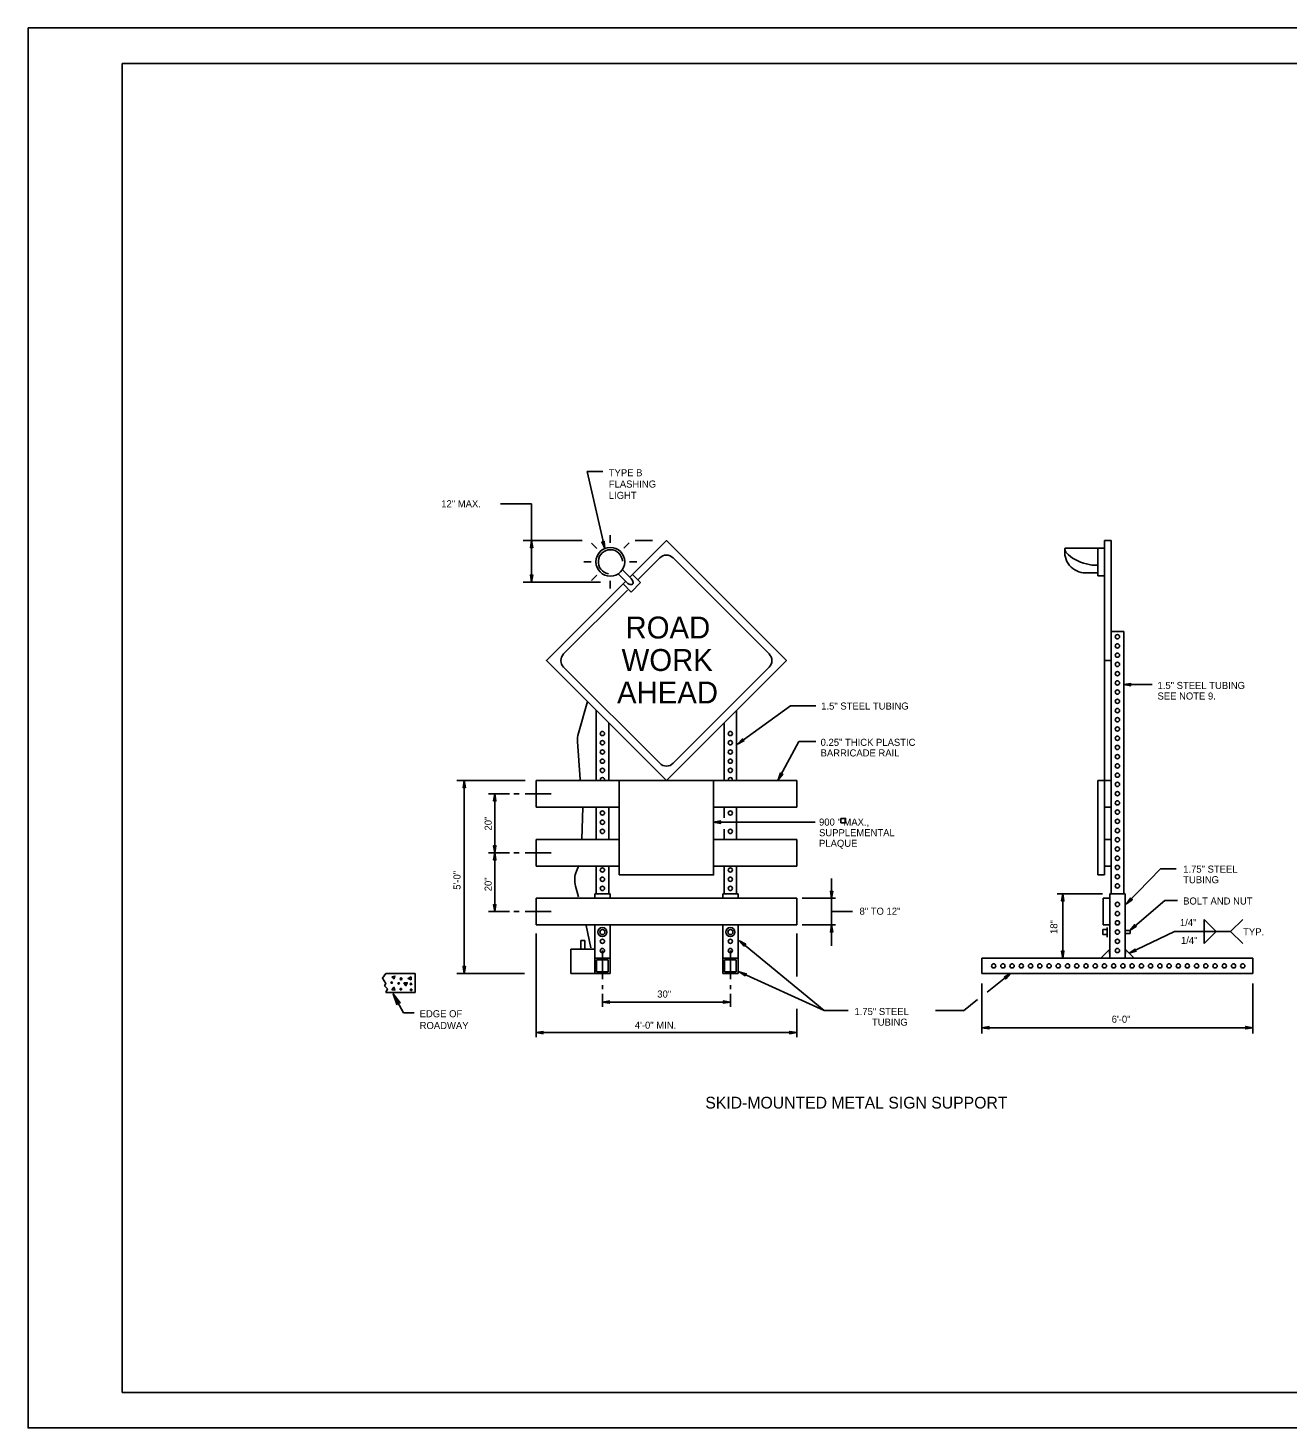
# Model space of a CAD drawing. Extents: x 641885 to 642934, y 293121 to 294294.
# Drawn here: x 641885 to 642420, y 293700 to 294294 of the extents above; entities that cross this region are included whole.
import ezdxf

# ---------------------------------------------------------------- set-up
doc = ezdxf.new("R2010")
doc.units = 0
for name, color, linetype in [('1', 7, 'Continuous'), ('Default', 7, 'Continuous'), ('Level 1', 7, 'Continuous'), ('Level 2', 7, 'Continuous'), ('Level 3', 7, 'Continuous'), ('PLT-BNDY', 7, 'Continuous')]:
    doc.layers.add(name, color=color, linetype=linetype)

# ---------------------------------------------------------------- blocks, each defined once
blk = doc.blocks.new('RARROW')
at = {"layer": 'Level 3'}
blk.add_lwpolyline([(-2.2695, 0.285), (-2.184875, 0.12075), (0, 0), (-2.2695, 0.285), (-2.38575, 0.384625), (0, 0), (-2.183125, -0.108), (-2.262875, -0.2705), (0, 0), (-2.38575, -0.379125), (-2.262875, -0.2705)], dxfattribs=at)

msp = doc.modelspace()

# ---------------------------------------------------------------- linework, layer by layer
at = {"layer": '1'}
for p, q in [((642384.2, 293910.28), (642384.2, 293915.37)), ((642389.3, 293910.28), (642384.2, 293915.37)), ((642395.44, 293910.28), (642400.54, 293915.37)), ((642371.58, 293910.28), (642395.44, 293910.28)), ((642384.2, 293910.28), (642384.2, 293905.18)), ((642389.3, 293910.28), (642384.2, 293905.18)), ((642395.44, 293910.28), (642400.54, 293905.18)), ((642040.24, 293883.86), (642044.56, 293875.8))]:
    msp.add_line(p, q, dxfattribs=at)
for points in [[(642037.06, 293892.46), (642035.66, 293890.45), (642037.02, 293888.25), (642036.56, 293887.27), (642037.78, 293885.98), (642037.06, 293884.47)], [(642041.88, 293879.59), (642042.09, 293879.89), (642040.24, 293883.86), (642041.88, 293879.59), (642041.81, 293879.29), (642040.24, 293883.86), (642042.49, 293880.11), (642042.85, 293880.13), (642040.24, 293883.86), (642043.16, 293880.01), (642042.85, 293880.13)]]:
    msp.add_lwpolyline(points, dxfattribs=at)
for points in [[(642039.67, 293890.98), (642040.96, 293891.36), (642040.65, 293890.22)], [(642044.74, 293888.56), (642046.18, 293888.56), (642045.58, 293887.27)], [(642047.77, 293891.06), (642047.77, 293889.84), (642046.56, 293890.37)], [(642039.59, 293885.6), (642040.96, 293885.45), (642040.5, 293886.66)]]:
    msp.add_lwpolyline(points, close=True, dxfattribs=at)
for centre, radius in [((642039.59, 293888.63), 0.321), ((642042.55, 293888.25), 0.321), ((642043.53, 293890.22), 0.408), ((642047.77, 293888.03), 0.321), ((642043.46, 293885.83), 0.321), ((642047.85, 293885.53), 0.321)]:
    msp.add_circle(centre, radius, dxfattribs=at)
at = {"layer": 'Default'}
for p, q in [((642049.48, 293892.46), (642037.06, 293892.46)), ((642049.48, 293892.46), (642049.48, 293884.47)), ((642049.48, 293884.47), (642037.06, 293884.47)), ((642044.56, 293875.8), (642049.17, 293875.8))]:
    msp.add_line(p, q, dxfattribs=at)
at = {"layer": 'Level 1'}
for p, q in [((641925.31, 294278.63), (642711.31, 294278.63)), ((641925.31, 294278.63), (641925.31, 293714.63)), ((642711.31, 293714.63), (641925.31, 293714.63)), ((641925.31, 293714.63), (642511.31, 293714.63))]:
    msp.add_line(p, q, dxfattribs=at)
at = {"layer": 'Level 2'}
for p, q in [((642122.46, 294105.39), (642129.1, 294105.39)), ((642122.46, 294105.39), (642129.94, 294072.78)), ((642085.79, 294091.69), (642098.9, 294091.69)), ((642098.9, 294091.69), (642098.9, 294058.57)), ((642132.3, 294075.22), (642132.28, 294078.43)), ((642095.3, 294076.13), (642120.37, 294076.13)), ((642126.6, 294072.84), (642124.32, 294075.09)), ((642138.01, 294072.88), (642140.27, 294075.15)), ((642142.84, 294076.13), (642150.19, 294076.13)), ((642325.24, 294072.95), (642341.94, 294072.95)), ((642339.12, 294072.95), (642339.12, 294061.13)), ((642341.94, 294076.13), (642341.94, 293974.31)), ((642341.94, 294076.13), (642344.76, 294076.13)), ((642344.76, 294076.13), (642344.76, 293974.31)), ((642124.25, 294067.12), (642121.05, 294067.11)), ((642140.4, 294067.18), (642143.6, 294067.19)), ((642153.27, 294068.8), (642144.17, 294059.69)), ((642199.67, 294028.05), (642158.92, 294068.8)), ((642126.56, 294061.44), (642124.31, 294059.17)), ((642139.37, 294058.38), (642135.7, 294062.06)), ((642141.1, 294060.1), (642137.42, 294063.78)), ((642145.17, 294058.29), (642141.71, 294061.75)), ((642333.91, 294062.46), (642339.12, 294062.46)), ((642339.12, 294061.13), (642341.94, 294061.13)), ((642095.3, 294058.57), (642128.15, 294058.57)), ((642139.64, 294055.17), (642112.52, 294028.05)), ((642132.29, 294059.04), (642132.3, 294055.84)), ((642141.18, 294054.31), (642137.73, 294057.77)), ((642141.18, 294054.31), (642145.17, 294058.29)), ((642344.76, 294037.6), (642350.06, 294037.6)), ((642350.06, 294037.6), (642350.06, 293926.28)), ((642341.94, 294025.22), (642344.76, 294025.22)), ((642112.52, 294022.39), (642153.27, 293981.65)), ((642158.92, 293981.65), (642199.67, 294022.39)), ((642350.06, 294015.06), (642362.08, 294015.06)), ((642122.69, 294007.93), (642118.76, 293994.37)), ((642126.31, 294004.1), (642126.31, 293974.31)), ((642185.88, 294004.1), (642185.88, 293974.31)), ((642208.67, 294005.98), (642186.27, 293989.8)), ((642208.67, 294005.98), (642219.48, 294005.98)), ((642131.61, 293998.79), (642131.61, 293974.31)), ((642180.58, 293998.79), (642180.58, 293974.31)), ((642118.39, 293990.87), (642119.53, 293974.79)), ((642212.27, 293990.85), (642203.55, 293974.67)), ((642212.27, 293990.85), (642219.44, 293990.85)), ((642067.19, 293974.31), (642096.15, 293974.31)), ((642070.37, 293892.46), (642070.37, 293974.31)), ((642100.79, 293974.31), (642136.1, 293974.31)), ((642100.79, 293974.31), (642100.79, 293963)), ((642211.4, 293974.31), (642176.1, 293974.31)), ((642211.4, 293974.31), (642211.4, 293963)), ((642339.12, 293974.31), (642344.76, 293974.31)), ((642339.12, 293974.31), (642339.12, 293934.31)), ((642341.94, 293974.31), (642341.94, 293934.31)), ((642344.76, 293974.31), (642344.76, 293926.28)), ((642089.48, 293968.66), (642080.61, 293968.66)), ((642083.3, 293943.69), (642083.3, 293968.66)), ((642093.67, 293968.66), (642091.45, 293968.66)), ((642107.21, 293968.66), (642096.13, 293968.66)), ((642100.79, 293963), (642136.1, 293963)), ((642120.7, 293963), (642120.25, 293949.34)), ((642126.31, 293963), (642126.31, 293949.34)), ((642131.61, 293963), (642131.61, 293949.34)), ((642211.4, 293963), (642176.1, 293963)), ((642180.58, 293963), (642180.58, 293958.46)), ((642185.88, 293963), (642185.88, 293949.34)), ((642341.94, 293963), (642344.76, 293963)), ((642176.1, 293956.68), (642219.2, 293956.68)), ((642180.58, 293953.71), (642180.58, 293949.34)), ((642100.79, 293949.34), (642136.1, 293949.34)), ((642100.79, 293949.34), (642100.79, 293938.03)), ((642211.4, 293949.34), (642176.1, 293949.34)), ((642211.4, 293949.34), (642211.4, 293938.03)), ((642341.94, 293949.34), (642344.76, 293949.34)), ((642089.48, 293943.69), (642080.61, 293943.69)), ((642083.3, 293918.71), (642083.3, 293943.69)), ((642093.67, 293943.69), (642091.45, 293943.69)), ((642107.21, 293943.69), (642096.13, 293943.69)), ((642100.79, 293938.03), (642136.1, 293938.03)), ((642118.95, 293938.35), (642117.95, 293935.92)), ((642126.31, 293938.03), (642126.31, 293926.28)), ((642131.61, 293938.03), (642131.61, 293926.28)), ((642211.4, 293938.03), (642176.1, 293938.03)), ((642180.58, 293938.03), (642180.58, 293926.28)), ((642185.88, 293938.03), (642185.88, 293926.28)), ((642341.94, 293938.03), (642344.76, 293938.03)), ((642351.23, 293921.97), (642365.7, 293936.86)), ((642365.7, 293936.86), (642372.29, 293936.86)), ((642117.56, 293929.5), (642118.78, 293925.03)), ((642226.18, 293924.37), (642226.18, 293932.79)), ((642339.12, 293934.31), (642341.94, 293934.31)), ((642100.79, 293924.37), (642211.4, 293924.37)), ((642100.79, 293924.37), (642100.79, 293913.06)), ((642132.21, 293926.28), (642125.71, 293926.28)), ((642125.71, 293924.37), (642125.71, 293926.28)), ((642132.21, 293924.37), (642132.21, 293926.28)), ((642186.48, 293926.28), (642179.98, 293926.28)), ((642179.98, 293924.37), (642179.98, 293926.28)), ((642186.48, 293924.37), (642186.48, 293926.28)), ((642211.4, 293924.37), (642211.4, 293913.06)), ((642213.69, 293924.37), (642227.87, 293924.37)), ((642226.18, 293913.06), (642226.18, 293924.37)), ((642321.91, 293926.28), (642341.05, 293926.28)), ((642324.23, 293898.96), (642324.23, 293926.28)), ((642344.16, 293924.37), (642341.34, 293924.37)), ((642341.34, 293924.37), (642341.34, 293913.06)), ((642344.16, 293926.28), (642344.16, 293898.96)), ((642344.16, 293926.28), (642350.66, 293926.28)), ((642350.66, 293926.28), (642350.66, 293898.96)), ((642352.77, 293910.89), (642367.46, 293923.42)), ((642367.46, 293923.42), (642372.86, 293923.42)), ((642089.48, 293918.71), (642080.61, 293918.71)), ((642093.67, 293918.71), (642091.45, 293918.71)), ((642107.21, 293918.71), (642096.13, 293918.71)), ((642226.18, 293918.71), (642235.1, 293918.71)), ((642100.79, 293913.06), (642211.4, 293913.06)), ((642122.07, 293912.89), (642124.01, 293903.39)), ((642125.71, 293892.46), (642125.71, 293913.06)), ((642132.21, 293892.46), (642132.21, 293913.06)), ((642179.98, 293892.46), (642179.98, 293913.06)), ((642186.48, 293892.46), (642186.48, 293913.06)), ((642213.69, 293913.06), (642227.87, 293913.06)), ((642226.18, 293904.26), (642226.18, 293913.06)), ((642344.16, 293913.06), (642341.34, 293913.06)), ((642343.07, 293912.02), (642343.07, 293907.92)), ((642100.79, 293865.41), (642100.79, 293909.38)), ((642119.86, 293902.8), (642119.86, 293906.5)), ((642119.86, 293906.5), (642121.46, 293906.5)), ((642121.46, 293902.8), (642121.46, 293906.5)), ((642223, 293876.74), (642187.13, 293906.38)), ((642211.4, 293891.25), (642211.4, 293909.38)), ((642343.07, 293911.11), (642341.23, 293911.11)), ((642341.23, 293911.11), (642341.23, 293908.97)), ((642343.07, 293908.97), (642341.23, 293908.97)), ((642352.82, 293910.66), (642350.66, 293910.66)), ((642352.82, 293909.42), (642350.66, 293909.42)), ((642352.41, 293901.05), (642371.58, 293910.28)), ((642352.82, 293910.66), (642352.82, 293909.42)), ((642115.61, 293902.8), (642125.71, 293902.8)), ((642115.61, 293902.8), (642115.61, 293892.46)), ((642125.71, 293902.8), (642125.71, 293892.46)), ((642128.96, 293890.04), (642128.96, 293902.21)), ((642183.23, 293890.04), (642183.23, 293902.21)), ((642132.21, 293898.96), (642125.71, 293898.96)), ((642126.46, 293893.21), (642126.46, 293898.21)), ((642131.46, 293898.21), (642126.46, 293898.21)), ((642131.46, 293893.21), (642131.46, 293898.21)), ((642186.48, 293898.96), (642179.98, 293898.96)), ((642180.73, 293893.21), (642180.73, 293898.21)), ((642185.73, 293898.21), (642180.73, 293898.21)), ((642185.73, 293893.21), (642185.73, 293898.21)), ((642289.96, 293898.96), (642404.86, 293898.96)), ((642289.96, 293898.96), (642289.96, 293892.46)), ((642404.86, 293898.96), (642404.86, 293892.46)), ((642067.19, 293892.46), (642095.88, 293892.46)), ((642115.61, 293892.46), (642125.71, 293892.46)), ((642132.21, 293892.46), (642125.71, 293892.46)), ((642131.46, 293893.21), (642126.46, 293893.21)), ((642128.96, 293885.8), (642128.96, 293887.52)), ((642186.48, 293892.46), (642179.98, 293892.46)), ((642185.73, 293893.21), (642180.73, 293893.21)), ((642183.23, 293885.8), (642183.23, 293887.52)), ((642223, 293876.74), (642187.02, 293893.19)), ((642289.96, 293892.46), (642404.86, 293892.46)), ((642289.96, 293867.01), (642289.96, 293888.2)), ((642292.13, 293884.57), (642302.1, 293892.46)), ((642404.86, 293867.01), (642404.86, 293888.2)), ((642128.96, 293878.34), (642128.96, 293883.89)), ((642183.23, 293878.34), (642183.23, 293883.89)), ((642128.96, 293880.31), (642183.23, 293880.31)), ((642211.4, 293865.41), (642211.4, 293877.44)), ((642223, 293876.74), (642233.15, 293876.74)), ((642270.25, 293876.74), (642282.25, 293876.74)), ((642282.18, 293876.69), (642288.11, 293881.38)), ((642100.79, 293867.38), (642211.4, 293867.38)), ((642289.96, 293869.48), (642404.86, 293869.48))]:
    msp.add_line(p, q, dxfattribs=at)
msp.add_lwpolyline([(642138.62, 294058.66), (642105.18, 294025.22), (642156.1, 293974.31), (642207.01, 294025.22), (642156.1, 294076.13), (642140.65, 294060.69)], dxfattribs=at)
for points in [[(642136.1, 293934.31), (642176.1, 293934.31), (642176.1, 293974.31), (642136.1, 293974.31)], [(642230.12, 293958.23), (642232.13, 293958.23), (642232.13, 293956.46), (642230.12, 293956.46)], [(642344.16, 293898.96), (642340.33, 293898.91), (642344.02, 293902.61)], [(642350.66, 293898.96), (642354.49, 293898.91), (642350.79, 293902.61)]]:
    msp.add_lwpolyline(points, close=True, dxfattribs=at)
for centre, radius in [((642132.33, 294067.15), 6.11), ((642347.41, 294035.36), 0.903), ((642347.41, 294031.44), 0.903), ((642347.41, 294027.52), 0.903), ((642347.41, 294023.61), 0.903), ((642347.41, 294019.69), 0.903), ((642347.41, 294015.77), 0.903), ((642347.41, 294011.86), 0.903), ((642347.41, 294007.94), 0.903), ((642347.41, 294004.03), 0.903), ((642347.41, 294000.11), 0.903), ((642128.96, 293994.29), 0.903), ((642183.23, 293994.29), 0.903), ((642347.41, 293996.19), 0.903), ((642128.96, 293990.38), 0.903), ((642183.23, 293990.38), 0.903), ((642347.41, 293992.28), 0.903), ((642347.41, 293988.36), 0.903), ((642128.96, 293986.46), 0.903), ((642128.96, 293982.54), 0.903), ((642183.23, 293986.46), 0.903), ((642183.23, 293982.54), 0.903), ((642347.41, 293984.45), 0.903), ((642128.96, 293978.63), 0.903), ((642183.23, 293978.63), 0.903), ((642347.41, 293980.53), 0.903), ((642347.41, 293976.61), 0.903), ((642347.41, 293972.7), 0.903), ((642347.41, 293968.78), 0.903), ((642347.41, 293964.87), 0.903), ((642128.96, 293960.56), 0.903), ((642183.23, 293960.56), 0.903), ((642347.41, 293960.95), 0.903), ((642128.96, 293956.65), 0.903), ((642128.96, 293952.73), 0.903), ((642183.23, 293952.73), 0.903), ((642347.41, 293957.03), 0.903), ((642347.41, 293953.12), 0.903), ((642347.41, 293949.2), 0.903), ((642347.41, 293945.28), 0.903), ((642347.41, 293941.37), 0.903), ((642128.96, 293936.39), 0.903), ((642183.23, 293936.39), 0.903), ((642347.41, 293937.45), 0.903), ((642128.96, 293932.47), 0.903), ((642128.96, 293928.56), 0.903), ((642183.23, 293932.47), 0.903), ((642183.23, 293928.56), 0.903), ((642347.41, 293933.54), 0.903), ((642347.41, 293929.62), 0.903), ((642347.41, 293921.79), 0.903), ((642347.41, 293917.87), 0.903), ((642128.96, 293910.04), 1.93), ((642183.23, 293910.04), 1.93), ((642347.41, 293913.96), 0.903), ((642128.96, 293910.04), 1.07), ((642128.96, 293906.12), 0.903), ((642183.23, 293910.04), 1.07), ((642183.23, 293906.12), 0.903), ((642347.41, 293910.04), 0.903), ((642347.41, 293906.12), 0.903), ((642128.96, 293902.21), 0.903), ((642183.23, 293902.21), 0.903), ((642347.41, 293902.21), 0.903), ((642294.91, 293895.71), 0.903), ((642298.83, 293895.71), 0.903), ((642302.74, 293895.71), 0.903), ((642306.66, 293895.71), 0.903), ((642310.58, 293895.71), 0.903), ((642314.49, 293895.71), 0.903), ((642318.41, 293895.71), 0.903), ((642322.32, 293895.71), 0.903), ((642326.24, 293895.71), 0.903), ((642330.16, 293895.71), 0.903), ((642334.07, 293895.71), 0.903), ((642337.99, 293895.71), 0.903), ((642341.9, 293895.71), 0.903), ((642345.82, 293895.71), 0.903), ((642349.74, 293895.71), 0.903), ((642353.65, 293895.71), 0.903), ((642357.57, 293895.71), 0.903), ((642361.49, 293895.71), 0.903), ((642365.4, 293895.71), 0.903), ((642369.32, 293895.71), 0.903), ((642373.23, 293895.71), 0.903), ((642377.07, 293895.71), 0.903), ((642380.99, 293895.71), 0.903), ((642384.9, 293895.71), 0.903), ((642388.82, 293895.71), 0.903), ((642392.74, 293895.71), 0.903), ((642396.65, 293895.71), 0.903), ((642400.57, 293895.71), 0.903)]:
    msp.add_circle(centre, radius, dxfattribs=at)
for centre, radius, start, end in [((642132.33, 294067.15), 5.12, 2.99859, 260.92051), ((642333.79, 294071.19), 8.73, 168.39588, 270.8338), ((642156.1, 294065.97), 4, 44.99999, 135), ((642115.35, 294025.22), 4, 135, 225), ((642196.84, 294025.22), 4, 314.99967, 44.99998), ((642128.36, 293991.58), 10, 163.81078, 184.07684), ((642156.1, 293984.48), 4, 224.99984, 315.0003), ((642128.96, 293974.71), 0.903, 350.18245, 189.46844), ((642183.23, 293974.71), 0.903, 350.53156, 189.81755), ((642127.21, 293932.13), 10, 157.72787, 195.25958)]:
    msp.add_arc(centre, radius, start, end, dxfattribs=at)
for centre, major_axis, ratio, start_param, end_param in [((642333.25, 294069.93), (8.01, -3.02), 0.375725, 3.141593, 5.588182), ((642140.23, 294059.24), (1.54, -1.54), 0.560008, 4.712389, 7.853982)]:
    msp.add_ellipse(centre, major_axis=major_axis, ratio=ratio, start_param=start_param, end_param=end_param, dxfattribs=at)
at = {"layer": 'PLT-BNDY'}
msp.add_lwpolyline([(641885.31, 294293.63), (642726.31, 294293.63), (642726.31, 293699.63), (641885.31, 293699.63)], close=True, dxfattribs=at)

# ---------------------------------------------------------------- block references
at = {"layer": 'Level 2'}
for p, xscale, yscale, rotation in [((642098.9, 294076.13), 1.2574347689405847, 1.3092961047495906, 89.99999999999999), ((642129.94, 294072.78), 1.257434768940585, 1.3092961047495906, -76.65647202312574), ((642098.9, 294058.57), 1.2574347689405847, 1.3092961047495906, -90.00000000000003), ((642350.06, 294015.06), 1.2574347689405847, 1.3092961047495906, 180), ((642186.26, 293989.8), 1.257434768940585, 1.3092961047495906, -143.95284350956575), ((642203.55, 293974.67), 1.2574347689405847, 1.3092961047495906, -118.29722389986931), ((642070.37, 293974.31), 1.2574347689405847, 1.3092961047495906, 89.99999999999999), ((642083.3, 293968.66), 1.2574347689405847, 1.3092961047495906, 89.99999999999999), ((642176.1, 293956.68), 1.2574347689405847, 1.3092961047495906, 180), ((642083.3, 293943.69), 1.2574347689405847, 1.3092961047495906, -90.00000000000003), ((642083.3, 293943.69), 1.2574347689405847, 1.3092961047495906, 89.99999999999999), ((642226.18, 293924.37), 1.2574347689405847, 1.3092961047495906, -90.00000000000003), ((642324.22, 293926.28), 1.2574347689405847, 1.3092961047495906, 89.99999999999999), ((642351.23, 293921.97), 1.2574347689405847, 1.3092961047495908, -134.20874209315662), ((642083.3, 293918.72), 1.2574347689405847, 1.3092961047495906, -90.00000000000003), ((642226.18, 293913.06), 1.2574347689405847, 1.3092961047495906, 89.99999999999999), ((642352.77, 293910.89), 1.2574347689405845, 1.3092961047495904, -139.54557767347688), ((642187.13, 293906.38), 1.2574347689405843, 1.3092961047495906, 140.2360200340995), ((642324.22, 293898.96), 1.2574347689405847, 1.3092961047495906, -90.00000000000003), ((642352.41, 293901.05), 1.2574347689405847, 1.3092961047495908, -154.2997184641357), ((642070.37, 293892.46), 1.2574347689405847, 1.3092961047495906, -90.00000000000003), ((642187.02, 293893.19), 1.2574347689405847, 1.3092961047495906, 155.22886209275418), ((642302.1, 293892.46), 1.257434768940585, 1.3092961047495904, 38.5772109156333), ((642128.96, 293880.31), 1.2574347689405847, 1.3092961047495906, 180), ((642289.96, 293869.48), 1.2574347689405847, 1.3092961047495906, 180), ((642100.79, 293867.38), 1.2574347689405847, 1.3092961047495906, 180)]:
    msp.add_blockref('RARROW', p, dxfattribs=dict(at, xscale=xscale, yscale=yscale, rotation=rotation))
at = {"layer": 'Level 2', "xscale": 1.2574347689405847, "yscale": 1.3092961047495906}
for p in [(642183.23, 293880.31), (642404.86, 293869.48), (642211.4, 293867.38)]:
    msp.add_blockref('RARROW', p, dxfattribs=at)

# ---------------------------------------------------------------- texts
at = {"layer": '1'}
for s, p in [('1/4"', (642373.92, 293912.59)), ('TYP.', (642400.72, 293908.65)), ('1/4"', (642374.37, 293905.02)), ('EDGE OF ', (642051.44, 293873.89)), ('ROADWAY', (642051.44, 293868.89))]:
    msp.add_text(s, height=3, dxfattribs=at).set_placement(p)
at = {"layer": 'Level 2'}
for s, height, p in [('TYPE B', 3, (642131.66, 294103.43)), ('FLASHING', 3, (642131.66, 294098.63)), ('LIGHT', 3, (642131.66, 294093.83)), ('12" MAX.', 3, (642060.6, 294090.27)), ('ROAD', 9.301, (642138.76, 294034.61)), ('WORK', 9.301, (642137.1, 294020.83)), ('AHEAD', 9.301, (642135.15, 294007.05)), ('1.5" STEEL TUBING', 3, (642364.42, 294013.19)), ('1.5" STEEL TUBING', 3, (642221.76, 294004.44)), ('SEE NOTE 9.', 3, (642364.42, 294008.69)), ('0.25" THICK PLASTIC', 3, (642221.52, 293989.05)), ('BARRICADE RAIL', 3, (642221.52, 293984.55)), ('SUPPLEMENTAL', 3, (642220.85, 293950.71)), ('900 " MAX.,', 3, (642220.85, 293955.21)), ('PLAQUE', 3, (642220.85, 293946.21)), ('1.75" STEEL', 3, (642375.31, 293935.26)), ('TUBING', 3, (642375.31, 293930.76)), ('BOLT AND NUT', 3, (642375.29, 293921.72)), ('8" TO 12"', 3, (642238.02, 293917.39)), ('30"', 3, (642152.22, 293882.25)), ('1.75" STEEL', 3, (642235.87, 293874.83)), ('4\'-0" MIN.', 3, (642142.7, 293869.04)), ('TUBING', 3, (642243.29, 293870.33)), ('6\'-0"', 3, (642344.97, 293871.57)), ('SKID-MOUNTED METAL SIGN SUPPORT', 5, (642172.6, 293835.17))]:
    msp.add_text(s, height=height, dxfattribs=at).set_placement(p)
for s, p in [('20"', (642081.97, 293953.14)), ('5\'-0"', (642068.77, 293928)), ('20"', (642081.97, 293927.36)), ('18"', (642321.95, 293909.22))]:
    msp.add_text(s, height=3, rotation=90, dxfattribs=at).set_placement(p)

doc.saveas('drawing.dxf')
